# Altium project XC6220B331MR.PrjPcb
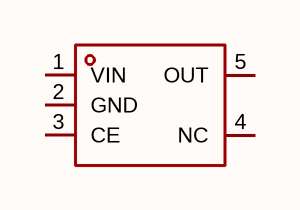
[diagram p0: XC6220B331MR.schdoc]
1 sheet, 1 parts. Net scope: global (net labels, ports and power ports of the same name join across sheets).

## Sheet XC6220B331MR.schdoc
size 127 x 101 mm

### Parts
U?  xc6220b331mr  [SOT-23-5_L2.9-W1.6-P0.95-LS2.8-BR]  (value not drawn)

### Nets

Not connected (* = marked no-connect by the designer): U? 1(VIN) 2(GND) 3(CE) 4(NC) 5(OUT)

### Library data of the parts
U? = xc6220b331mr: 输出极性:正极;工作电压:5.5V;输出电压:3.3V;输出电流:900mA;电源纹波抑制比(PSRR):50dB@(10kHz);输出类型:固定;; Manufacturer: TECH PUBLIC(台舟); AddInBom: yes; ModelId: 7ba65df16e7b4570af156e925f9c37fe; ModelTransform: 114.173,114.173,0,90,0,0,0,0,0; Output Configuration: 正极; Voltage - Supply: 5.5V; Output Voltage: 3.3V; Output Current: 900mA; Voltage Dropout: 400mV@(800mA); standby current: 25uA; Output Type: 固定; Number of Outputs: 1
